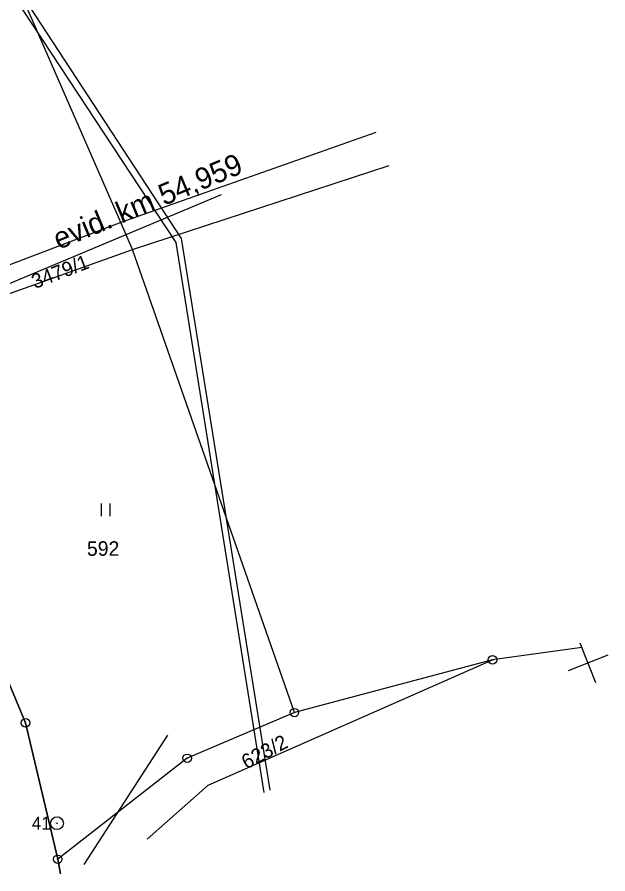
# Model space of a CAD drawing. Extents: x -834059 to -833839, y -1109191 to -1108937.
# Drawn here: x -833907.9 to -833838.7, y -1109158.6 to -1109058.2 of the extents above; entities that cross this region are included whole.
import ezdxf

# ---------------------------------------------------------------- set-up
doc = ezdxf.new("R2010")
doc.units = 0
for name, color, linetype in [('230i_elektrické vedení_DZKlatovy_digi', 7, 'Continuous'), ('230i_vodovod_DZKlatovy_digi', 7, 'Continuous'), ('Hranice parcel', 7, 'Continuous'), ('Parcelní čísla', 7, 'Continuous'), ('Vrstva 4', 7, 'Continuous'), ('Vrstva 49', 7, 'Continuous'), ('Vrstva 53', 7, 'Continuous'), ('Vrstva 60', 7, 'Continuous'), ('Značky bodu BP', 7, 'Continuous'), ('Značky kultur', 7, 'Continuous')]:
    doc.layers.add(name, color=color, linetype=linetype)

msp = doc.modelspace()

# ---------------------------------------------------------------- linework, layer by layer
at = {"layer": '230i_elektrické vedení_DZKlatovy_digi'}
for p, q in [((-833888.67, -1109084.15), (-833911.65, -1109049.06)), ((-833878.27, -1109148.79), (-833888.67, -1109084.15))]:
    msp.add_line(p, q, dxfattribs=at)
at = {"layer": '230i_vodovod_DZKlatovy_digi'}
for p, q in [((-833889.3, -1109084.62), (-833912.5, -1109049.39)), ((-833878.99, -1109149.08), (-833889.3, -1109084.62))]:
    msp.add_line(p, q, dxfattribs=at)
at = {"layer": 'Hranice parcel'}
for p, q in [((-833895.8, -1109082.28), (-833910.52, -1109048.6)), ((-833895.8, -1109082.28), (-833923.74, -1109092.89)), ((-833894.43, -1109085.46), (-833895.8, -1109082.28)), ((-833925.47, -1109096.55), (-833894.43, -1109085.46)), ((-833875.45, -1109139.72), (-833894.43, -1109085.46)), ((-833841.75, -1109132.08), (-833852.22, -1109133.54)), ((-833852.22, -1109133.54), (-833875.45, -1109139.72)), ((-833902.86, -1109158.62), (-833903.19, -1109156.91))]:
    msp.add_line(p, q, dxfattribs=at)
for points in [[(-833865.88, -1109071.72), (-833895.8, -1109082.28)], [(-833894.43, -1109085.46), (-833864.32, -1109075.62)], [(-833903.19, -1109156.91), (-833906.97, -1109140.92), (-833924.59, -1109098.65), (-833925.47, -1109096.55)], [(-833892.7, -1109154.56), (-833885.55, -1109148.22), (-833852.22, -1109133.54)], [(-833875.45, -1109139.72), (-833888.01, -1109145.07), (-833903.19, -1109156.91)]]:
    msp.add_lwpolyline(points, dxfattribs=at)
at = {"layer": 'Vrstva 4'}
msp.add_line((-833942.95, -1109103.69), (-833883.99, -1109079), dxfattribs=at)
at = {"layer": 'Vrstva 49'}
msp.add_lwpolyline([(-833900.1, -1109157.52), (-833890.3, -1109142.36)], dxfattribs=at)
at = {"layer": 'Vrstva 53'}
msp.add_lwpolyline([(-833927.77, -1109091.16), (-833926.57, -1109093.96), (-833925.47, -1109096.55), (-833924.59, -1109098.65), (-833906.97, -1109140.92), (-833903.19, -1109156.91), (-833902.86, -1109158.62)], dxfattribs=at)
at = {"layer": 'Vrstva 60'}
for p, q in [((-833840.09, -1109136.22), (-833841.95, -1109131.58)), ((-833838.7, -1109132.97), (-833843.34, -1109134.83))]:
    msp.add_line(p, q, dxfattribs=at)
at = {"layer": 'Značky bodu BP'}
for centre, radius in [((-833852.22, -1109133.54), 0.5), ((-833852.22, -1109133.54), 0.0303), ((-833875.45, -1109139.72), 0.5), ((-833875.45, -1109139.72), 0.0303), ((-833906.97, -1109140.92), 0.5), ((-833906.97, -1109140.92), 0.0303), ((-833888.01, -1109145.07), 0.5), ((-833888.01, -1109145.07), 0.0303), ((-833903.27, -1109152.68), 0.75), ((-833903.27, -1109152.68), 0.03), ((-833903.19, -1109156.91), 0.5), ((-833903.19, -1109156.91), 0.0303)]:
    msp.add_circle(centre, radius, dxfattribs=at)
at = {"layer": 'Značky kultur'}
for p, q in [((-833898.04, -1109116.7), (-833898.04, -1109115.2)), ((-833897.04, -1109116.7), (-833897.04, -1109115.2))]:
    msp.add_line(p, q, dxfattribs=at)

# ---------------------------------------------------------------- texts
at = {"layer": 'Parcelní čísla'}
for s, rotation, p in [('3479/1', 21, (-833905.86, -1109090.08)), ('623/2', 28, (-833881.07, -1109146.39))]:
    msp.add_text(s, height=1.7, rotation=rotation, dxfattribs=at).set_placement(p)
msp.add_text('592', height=1.7, dxfattribs=at).set_placement((-833899.76, -1109121.34))
at = {"layer": 'Vrstva 4'}
msp.add_text('evid. km 54,959', height=2.5, rotation=22.6411, dxfattribs=at).set_placement((-833903.07, -1109085.49))
at = {"layer": 'Značky bodu BP'}
msp.add_text('41', height=1.5, dxfattribs=at).set_placement((-833906.23, -1109153.43))

doc.saveas('drawing.dxf')
